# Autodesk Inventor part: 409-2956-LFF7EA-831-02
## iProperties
Created: 2010-09
Part Number: 409-2956-LFF7EA-831-02
Material: 3/8"OD TUBE - SS
Document SubType Name: Modeling
Designer: S. Boerckel
Engineer: Steve Boerckel
Mass: 166.544 g
Surface Area: 342.312 cm^2
Volume: 20.6119 cm^3
Density: 8.08 g/cm^3
Description: LOW PRESSURE GAUGE TUBE
LGTH: 21.836 in
Author: S. Boerckel
Revision Number: 0
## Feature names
1. Sweep1
